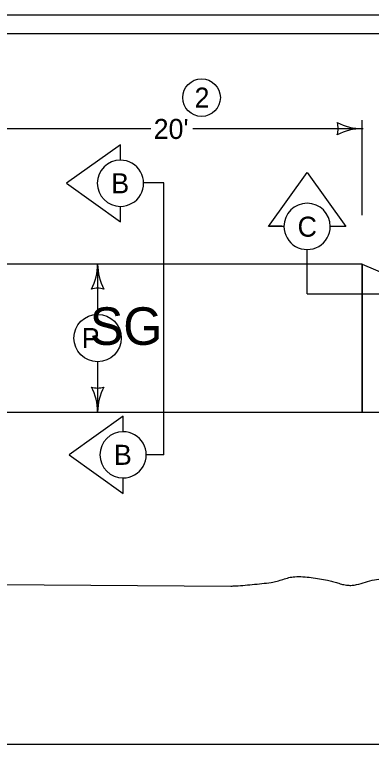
# Model space of a CAD drawing. Extents: x 9538 to 81668, y 7600 to 11751.
# Drawn here: x 11524 to 11808, y 9349 to 9944 of the extents above; entities that cross this region are included whole.
import ezdxf

# ---------------------------------------------------------------- set-up
doc = ezdxf.new("R2010")
doc.units = 0
for name, color, linetype in [('Default', 7, 'Continuous'), ('DsnShtMinorGrid13', 7, 'Continuous'), ('dsnStdDimension', 7, 'Continuous'), ('dsnStdNameDate', 7, 'Continuous'), ('dsnStdPattern', 7, 'Continuous'), ('dsnStdShading', 7, 'Continuous'), ('dsnStdTable', 7, 'Continuous')]:
    doc.layers.add(name, color=color, linetype=linetype)

msp = doc.modelspace()

# ---------------------------------------------------------------- linework, layer by layer
at = {"layer": 'Default'}
msp.add_lwpolyline([(10132.52, 9944.02), (13267.53, 9944.02), (13267.53, 7924.02), (10132.52, 7924.02)], close=True, dxfattribs=at)
at = {"layer": 'DsnShtMinorGrid13'}
msp.add_circle((11672.55, 9877.91), 15, dxfattribs=at)
at = {"layer": 'dsnStdDimension'}
for p, q in [((11800.84, 9783.96), (11800.84, 9859.98)), ((11496.09, 9853.15), (11632.09, 9853.15)), ((11665.62, 9853.15), (11801.62, 9853.15)), ((11589.59, 9744.89), (11589.59, 9704.71)), ((11589.59, 9666.84), (11589.59, 9626.66))]:
    msp.add_line(p, q, dxfattribs=at)
msp.add_circle((11589.59, 9685.77), 18.93, dxfattribs=at)
for centre, radius, start, end in [((11765.2, 9853.15), 16.42, 342.26665, 17.73335), ((11800.84, 9895.65), 42.5, 241.92751, 270), ((11800.84, 9810.65), 42.5, 90, 118.07249), ((11547.09, 9744.89), 42.5, 331.92751, 0), ((11632.09, 9744.89), 42.5, 180, 208.07249), ((11589.59, 9709.25), 16.42, 72.26665, 107.73335), ((11589.59, 9662.29), 16.42, 252.26665, 287.73335), ((11547.09, 9626.66), 42.5, 360, 28.07249), ((11632.09, 9626.66), 42.5, 151.92751, 180)]:
    msp.add_arc(centre, radius, start, end, dxfattribs=at)
at = {"layer": 'dsnStdNameDate'}
for p, q in [((11800.84, 9744.89), (11496.09, 9744.89)), ((11800.84, 9626.66), (11800.84, 9744.89)), ((11496.09, 9626.66), (11800.84, 9626.66)), ((12303.1, 9361.02), (10147.52, 9361.02))]:
    msp.add_line(p, q, dxfattribs=at)
msp.add_circle((11589.59, 9685.77), 18.93, dxfattribs=at)
at = {"layer": 'dsnStdPattern'}
for p, q in [((11642.35, 9809.76), (11626.57, 9809.76)), ((11642.35, 9592.47), (11642.35, 9809.76)), ((11756.78, 9721.12), (11756.78, 9756.56)), ((11756.78, 9721.12), (11844.89, 9721.12)), ((11642.35, 9592.47), (11628.39, 9592.47))]:
    msp.add_line(p, q, dxfattribs=at)
for points in [[(11607.78, 9827.94), (11607.78, 9840.26), (11564.65, 9809.45), (11607.78, 9778.64), (11607.78, 9790.97)], [(11738.3, 9775.05), (11725.97, 9775.05), (11756.78, 9818.18), (11787.59, 9775.05), (11775.27, 9775.05)], [(11609.91, 9610.96), (11609.91, 9623.28), (11566.77, 9592.47), (11609.91, 9561.66), (11609.91, 9573.99)]]:
    msp.add_lwpolyline(points, dxfattribs=at)
for centre, start, end in [((11607.79, 9809.45), 90.00083, 269.99917), ((11607.79, 9809.45), 269.99917, 90.00083), ((11756.78, 9775.05), 0.00083, 179.99917), ((11756.78, 9775.05), 179.99917, 0.00083), ((11609.91, 9592.47), 90.00083, 269.99917), ((11609.91, 9592.47), 269.99917, 90.00083)]:
    msp.add_arc(centre, 18.49, start, end, dxfattribs=at)
at = {"layer": 'dsnStdShading'}
msp.add_line((10147.52, 9929.02), (13243.21, 9929.02), dxfattribs=at)
at = {"layer": 'dsnStdTable'}
for p, q in [((11736.7, 9775.2), (11727.46, 9775.28)), ((11736.7, 9775.2), (11730.09, 9775.26)), ((11800.84, 9744.89), (11496.09, 9744.89)), ((11800.84, 9744.89), (11800.84, 9626.66)), ((11800.84, 9744.89), (11904.87, 9700.29)), ((10364.45, 9626.66), (11977.72, 9626.66)), ((11366.68, 9490.03), (11695.88, 9487.58))]:
    msp.add_line(p, q, dxfattribs=at)
msp.add_spline([(11695.88, 9487.58), (11697.88, 9487.69), (11705.46, 9488.17), (11713.02, 9488.83), (11720.57, 9489.63), (11728.11, 9490.54), (11732.85, 9491.54), (11737.54, 9492.98), (11742.21, 9494.34), (11744.56, 9494.83), (11746.92, 9495.1), (11753.46, 9495.09), (11760.05, 9494.43), (11766.64, 9493.39), (11773.15, 9492.25), (11777.16, 9491.31), (11781.14, 9490.11), (11785.12, 9488.98), (11789.12, 9488.26), (11792.67, 9488.23), (11796.22, 9488.73), (11803.32, 9490.66), (11810.46, 9492.67), (11817.63, 9493.39), (11832.17, 9492.42), (11846.71, 9491.11), (11853.43, 9490.29), (11860.14, 9489.3), (11866.83, 9488.36), (11873.51, 9487.69), (11879.27, 9488.25), (11884.94, 9490.08), (11890.61, 9492.13), (11896.32, 9493.39), (11903.82, 9493.9), (11911.43, 9494.03), (11922.81, 9493.33), (11926.55, 9492.82), (11933.57, 9491), (11940.46, 9488.43), (11947.38, 9486.06), (11954.49, 9484.83), (11975.59, 9483.83)], degree=3, dxfattribs=at)

# ---------------------------------------------------------------- texts
at = {"layer": 'DsnShtMinorGrid13'}
msp.add_text('2', height=16, dxfattribs=at).set_placement((11666.97, 9869.91))
at = {"layer": 'dsnStdDimension'}
for s, height, p in [("20'", 16, (11634.33, 9844.87)), ('SG', 30, (11583.31, 9680.33)), ('P', 16, (11576.87, 9677.77))]:
    msp.add_text(s, height=height, dxfattribs=at).set_placement(p)
at = {"layer": 'dsnStdPattern'}
for s, p in [('B', (11600.51, 9801.45)), ('C', (11749.16, 9766.78)), ('B', (11602.61, 9584.47))]:
    msp.add_text(s, height=16, dxfattribs=at).set_placement(p)

doc.saveas('drawing.dxf')
